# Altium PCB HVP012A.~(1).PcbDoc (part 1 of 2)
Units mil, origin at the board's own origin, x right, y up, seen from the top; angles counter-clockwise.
Board outline 2249 x 2178 mil, 4 copper layers (Top Layer, MidLayer1, MidLayer2, Bottom Layer), stack 61.2 mil thick; 92 components, 29 nets, 189 pads, 191 vias.
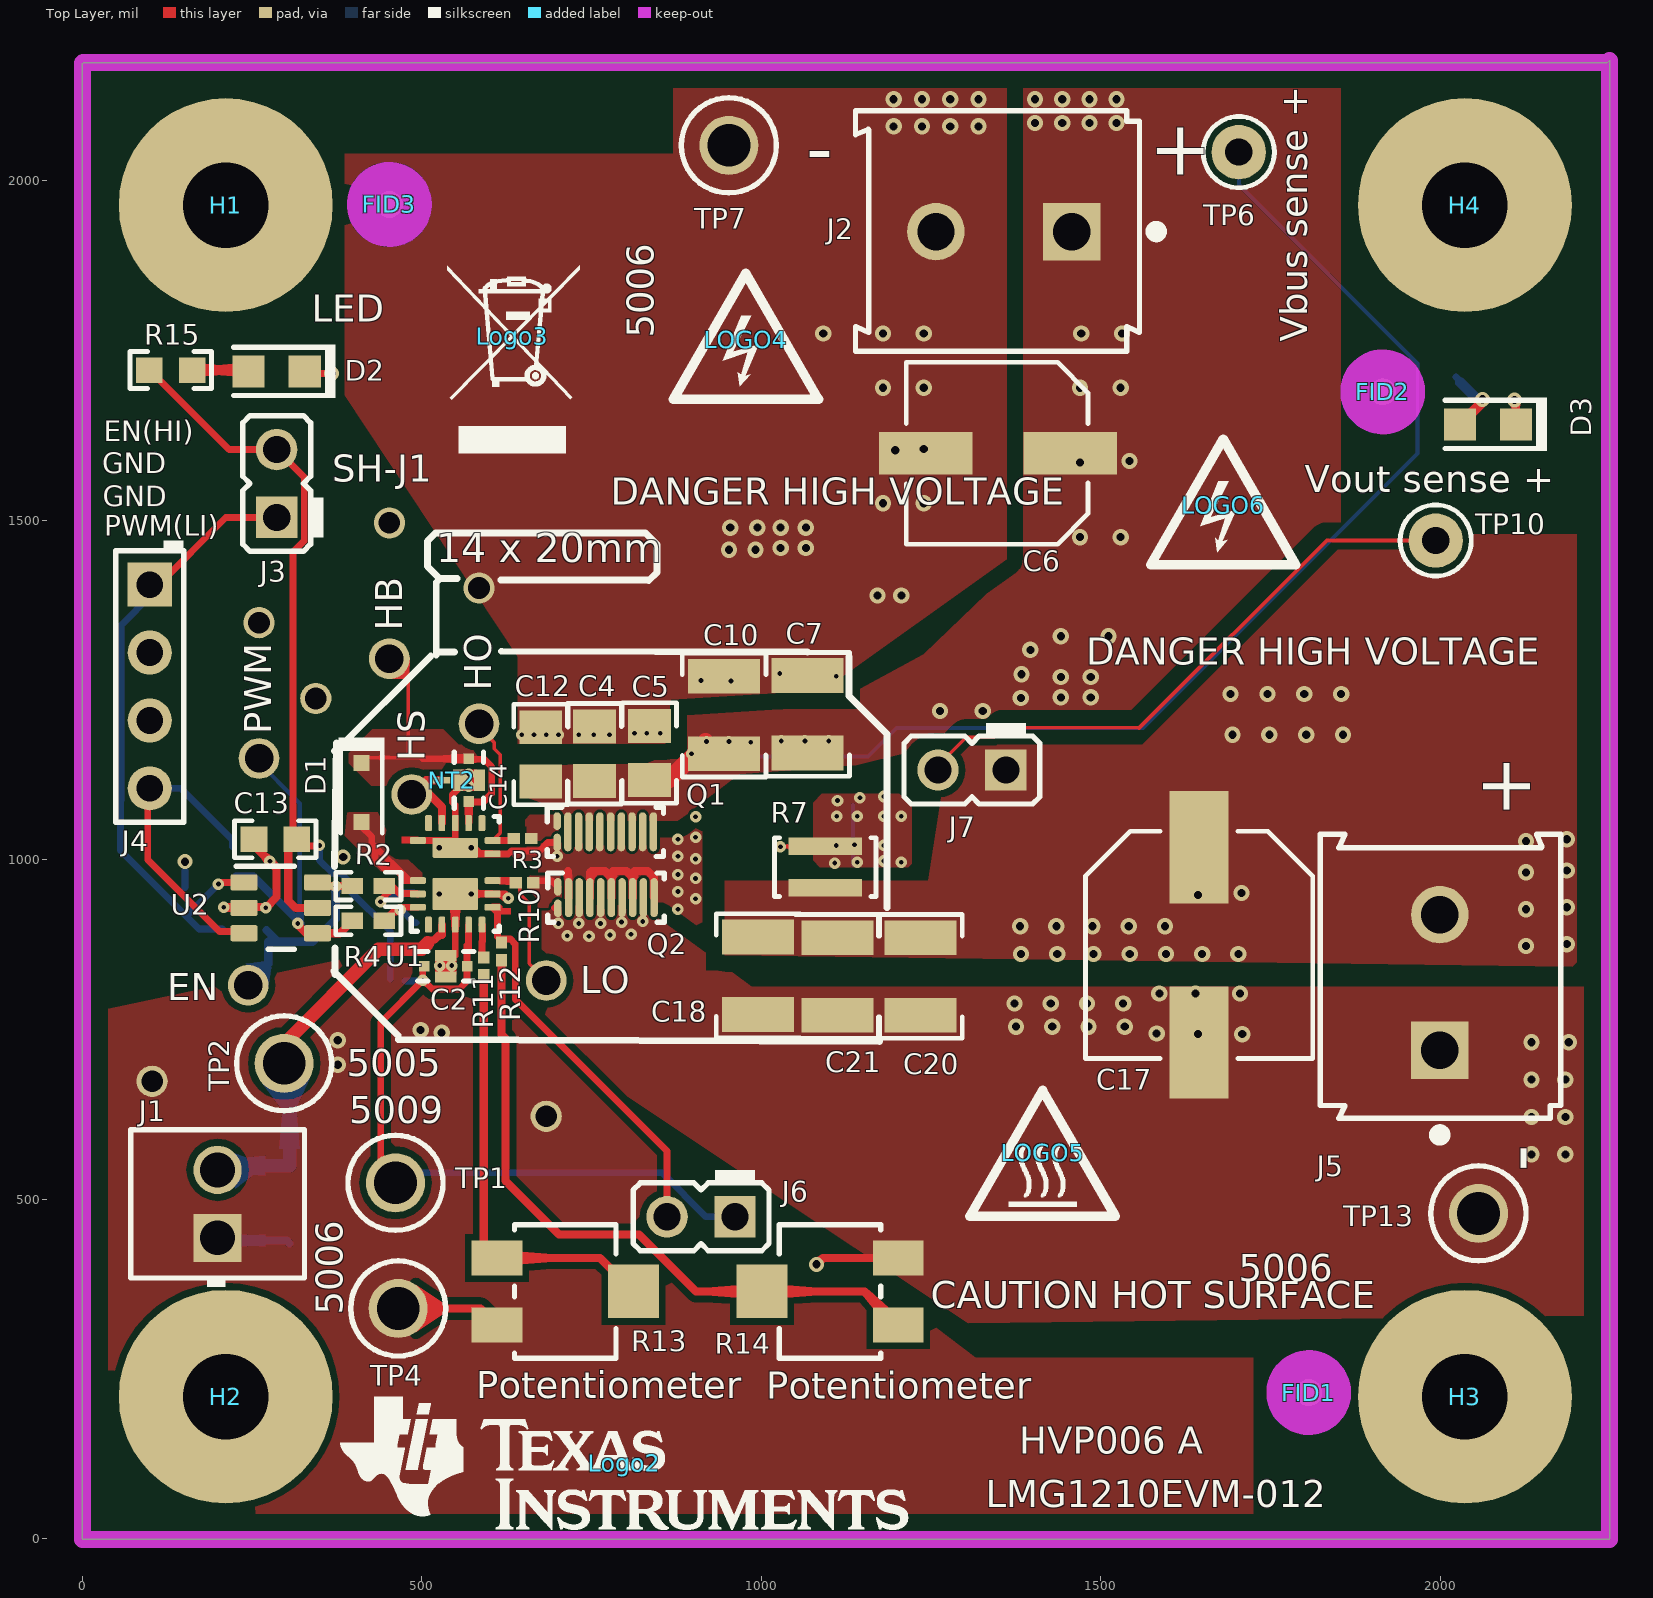
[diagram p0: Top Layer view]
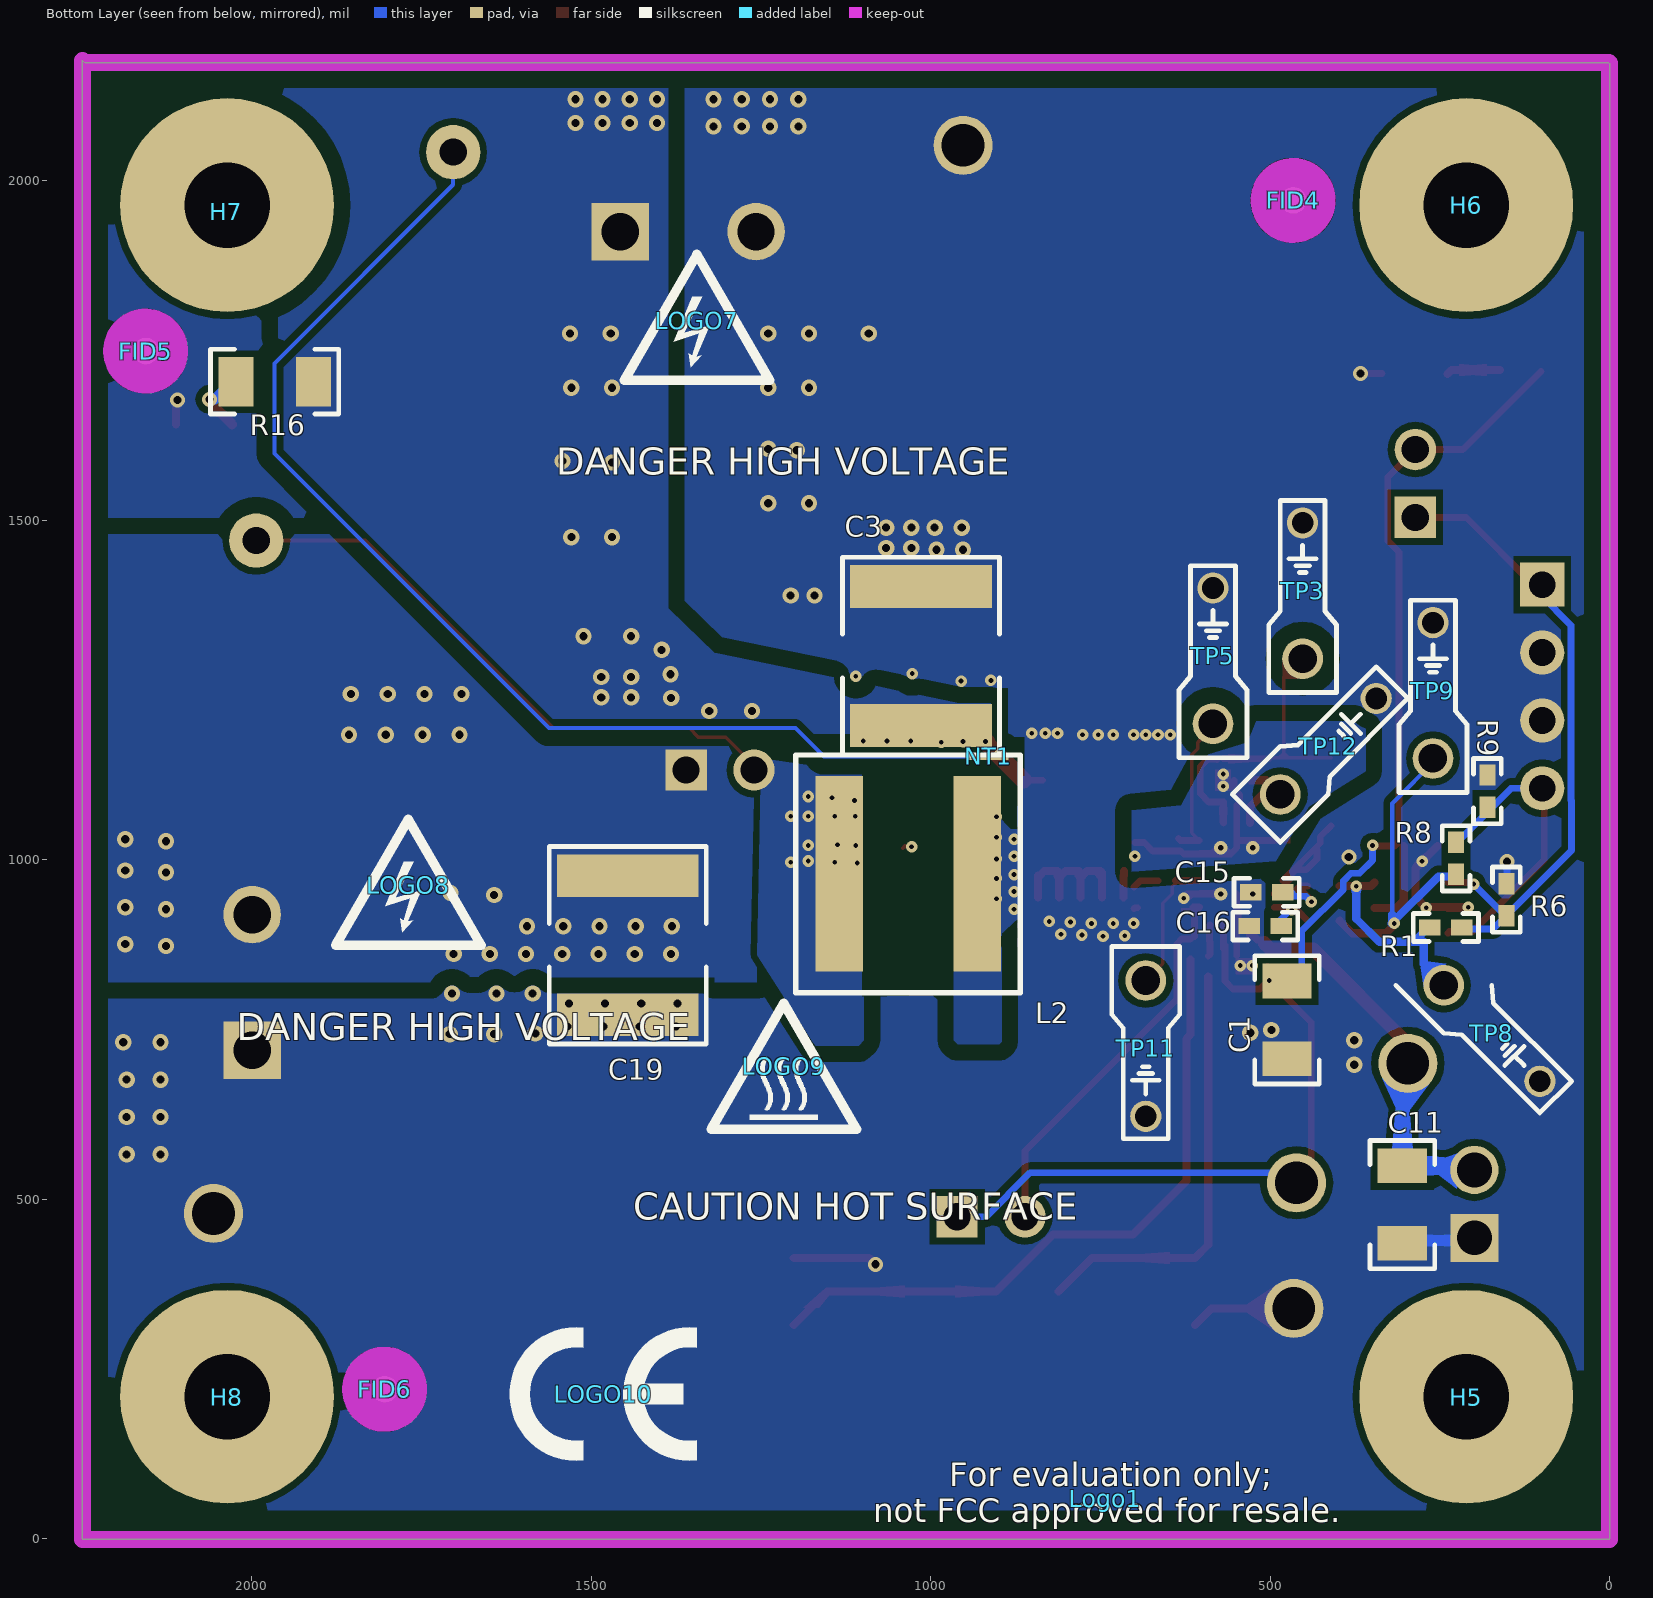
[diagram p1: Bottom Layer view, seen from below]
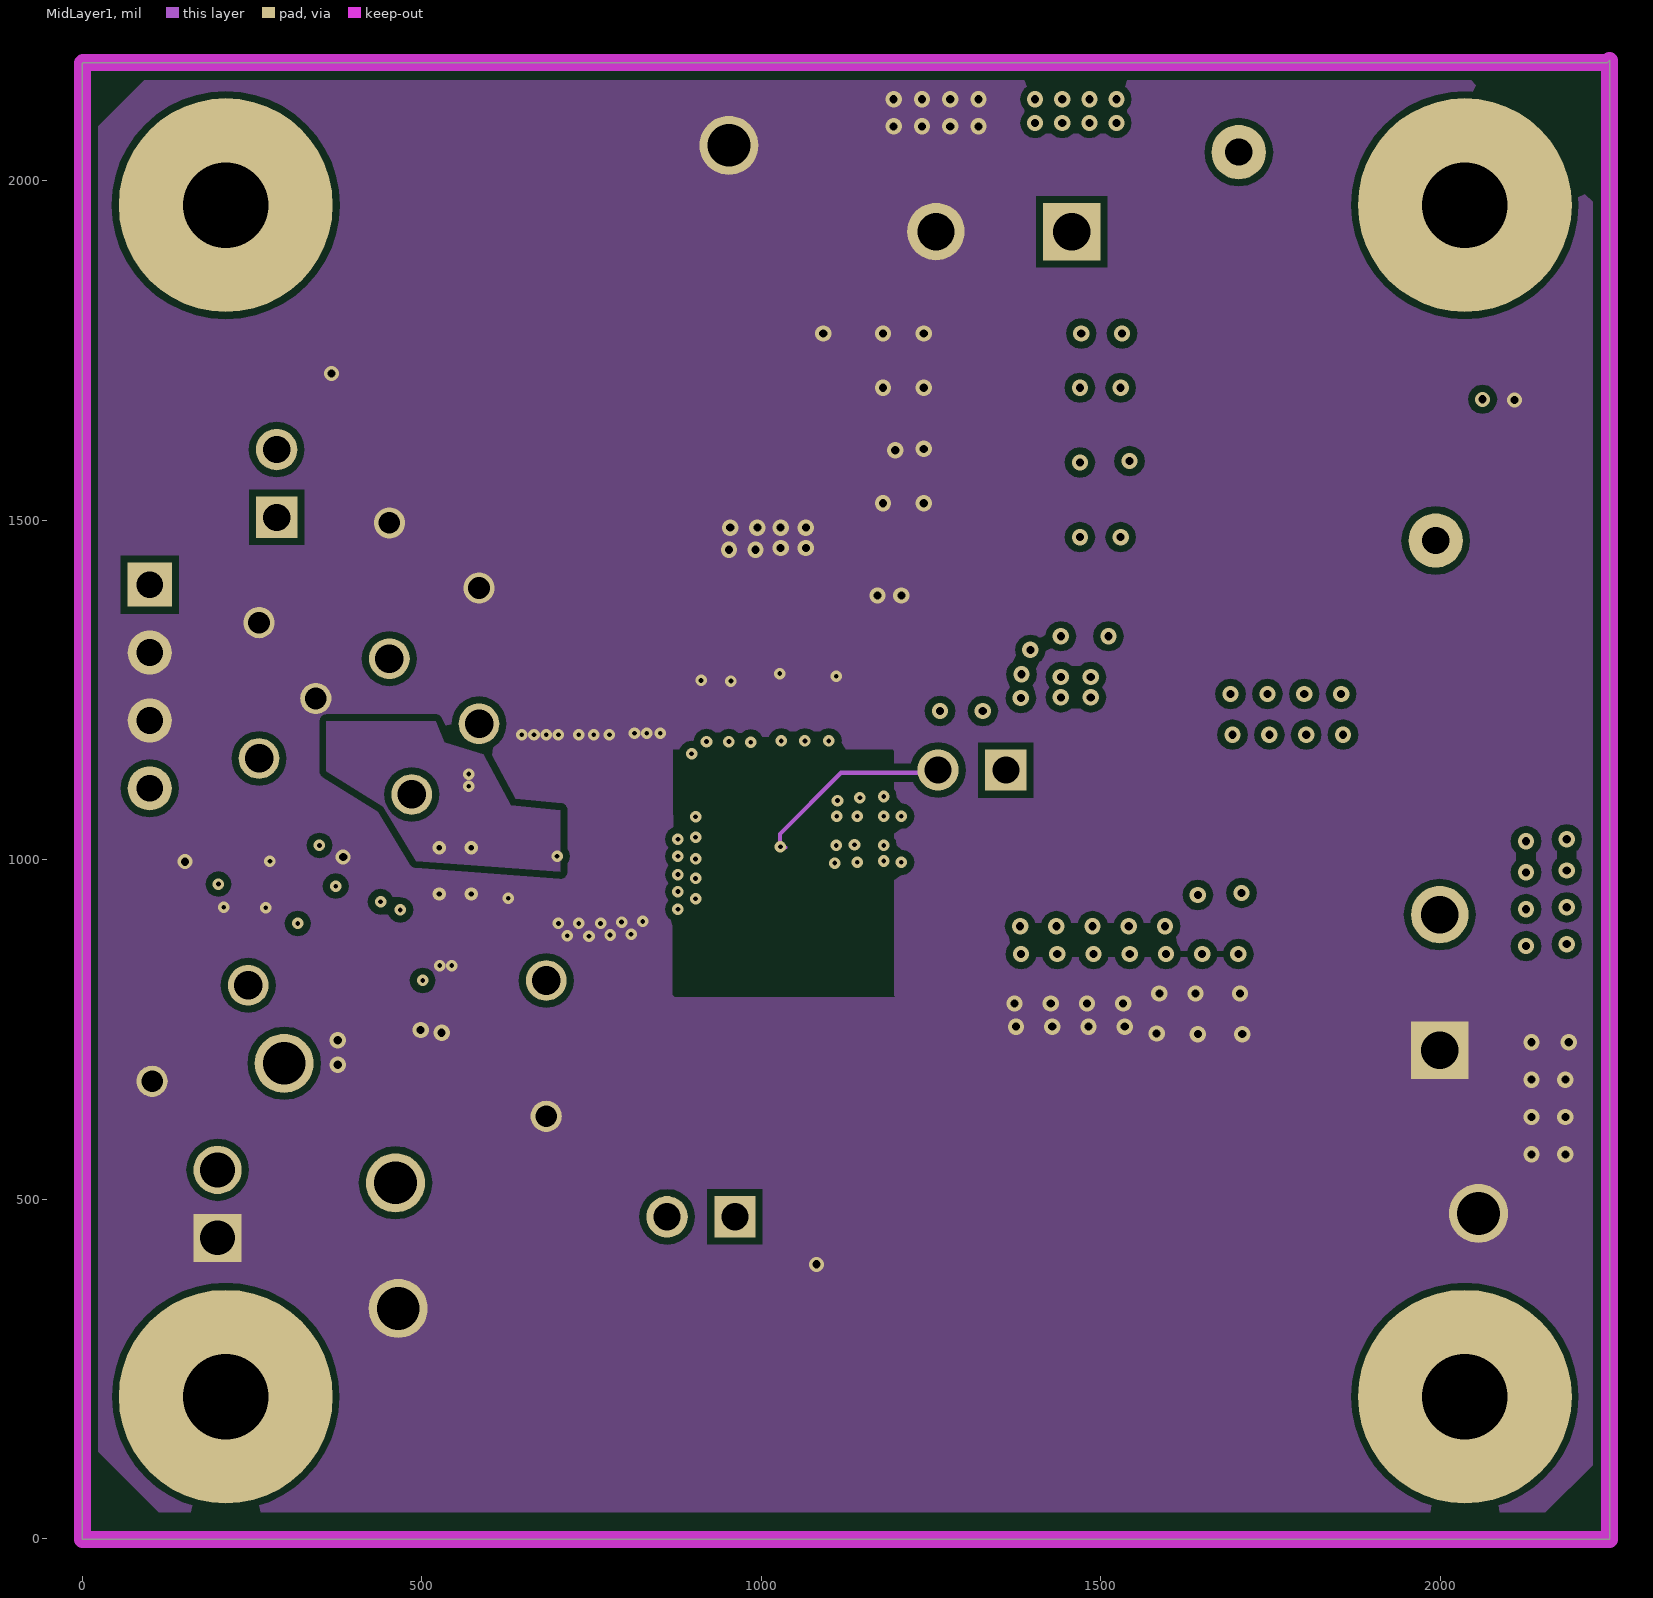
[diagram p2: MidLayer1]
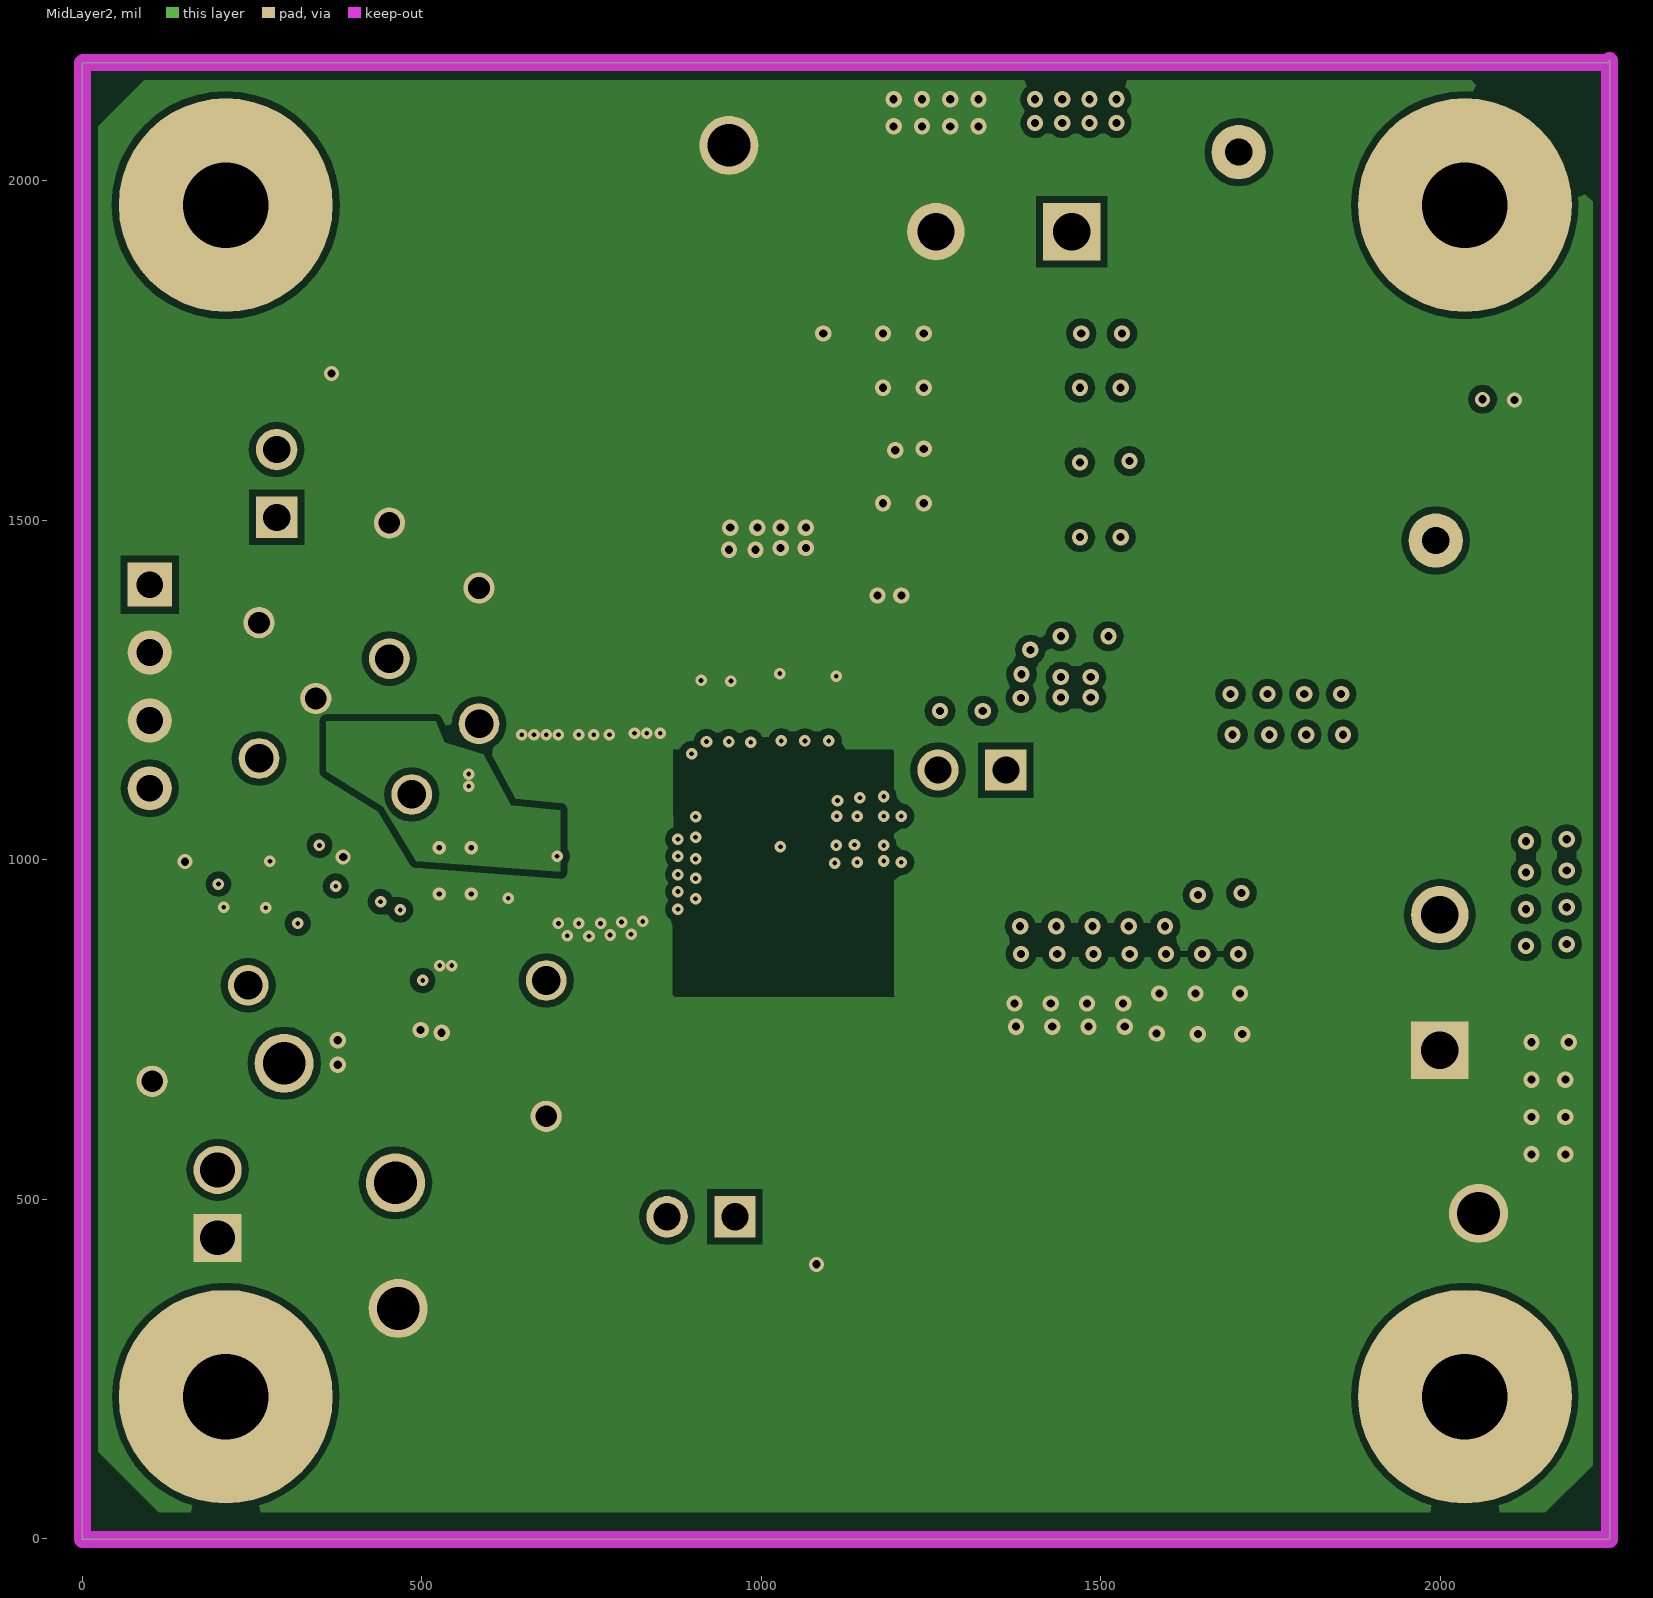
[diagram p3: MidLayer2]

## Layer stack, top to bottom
Top Solder: solder mask 0.4, Solder Resist, Dk 3.5
Top Layer: signal copper 2.8
Dielectric1: core 5, FR-4, Dk 4.2
MidLayer1: signal copper 2.8
Dielectric2: core 40, FR-4, Dk 4.2
MidLayer2: signal copper 2.8
Dielectric 3: prepreg 5, Dk 4.2
Bottom Layer: signal copper 2.8
Bottom Solder: solder mask 0.4, Solder Resist, Dk 3.5

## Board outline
0,-1 0,2173 1,2174 2246,2174 2249,2177 2249,-1

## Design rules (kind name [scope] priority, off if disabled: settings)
AcuteAngle [All] p1: minimum=3.20000000000000E+0001 checktracksonly=FALSE
AssemblyTestPointUsage [All] p1: valid=2
Clearance Fiducials [HasFootprint('Fiducial10-30')] p1: gap=0 ignorepadtopadclearanceinfootprint=FALSE
Clearance "inner layer clearance" [OnLayer('MidLayer1')or OnLayer('MidLayer2')] p2: gap=10 ignorepadtopadclearanceinfootprint=FALSE except(0: Arc-Hole Track-Hole SMDPad-Hole THPad-Hole Via-Hole Fill-Hole Poly-Hole Region-Hole Text-Hole)
Clearance Clearance_BoardEdge_Poly [OnCopper and InPoly vs IsKeepOut] p3: gap=25 ignorepadtopadclearanceinfootprint=FALSE except(0: Arc-Hole Track-Hole SMDPad-Hole THPad-Hole Via-Hole Fill-Hole Poly-Hole Region-Hole Text-Hole)
Clearance Clearance_BoardEdge [OnCopper and Not InComponentClass('Logo') and not InComponentClass('FiducialMark') and not InRegion(1000,500,4000,800) and Not OnLayer('Keepout') vs OnLayer('Keepout')] p4: gap=60 ignorepadtopadclearanceinfootprint=FALSE except(0: Arc-Hole Track-Hole SMDPad-Hole THPad-Hole Via-Hole Fill-Hole Poly-Hole Region-Hole Text-Hole)
Clearance Clearance_BoardEdge_MountingHoles [OnCopper and InComponentClass('Mounting Holes') vs IsKeepOut] p5: gap=40 ignorepadtopadclearanceinfootprint=FALSE except(0: Arc-Hole Track-Hole SMDPad-Hole THPad-Hole Via-Hole Fill-Hole Poly-Hole Region-Hole Text-Hole)
Clearance "FET pads clearance" [All vs WithinRoom('FETs')] p6: gap=4 ignorepadtopadclearanceinfootprint=FALSE except(0: Arc-Hole Track-Hole SMDPad-Hole THPad-Hole Via-Hole Fill-Hole Poly-Hole Region-Hole Text-Hole)
Clearance SW [InNetClass('SW') vs not InNetClass('SW')] p7: gap=24 ignorepadtopadclearanceinfootprint=FALSE except(0: Arc-Hole Track-Hole SMDPad-Hole THPad-Hole Via-Hole Fill-Hole Poly-Hole Region-Hole Text-Hole)
Clearance HV [InNetClass('HV') vs not InNetClass('HV')] p8: gap=24 ignorepadtopadclearanceinfootprint=FALSE except(0: Arc-Hole Track-Hole SMDPad-Hole THPad-Hole Via-Hole Fill-Hole Poly-Hole Region-Hole Text-Hole)
Clearance HV2 [InNetClass('HV2') vs not InNetClass('HV2')] p9: gap=24 ignorepadtopadclearanceinfootprint=FALSE except(0: Arc-Hole Track-Hole SMDPad-Hole THPad-Hole Via-Hole Fill-Hole Poly-Hole Region-Hole Text-Hole)
Clearance Clearance_Poly [InPolygon] p10: gap=10 ignorepadtopadclearanceinfootprint=FALSE except(0: Arc-Hole Track-Hole SMDPad-Hole THPad-Hole Via-Hole Fill-Hole Poly-Hole Region-Hole Text-Hole)
Clearance Clearance_1 [All] p11: gap=5 ignorepadtopadclearanceinfootprint=FALSE except(0: Arc-Hole Track-Hole SMDPad-Hole THPad-Hole Via-Hole Fill-Hole Poly-Hole Region-Hole Text-Hole)
ComponentClearance [InComponent('SH-J1')] p1: gap=0 collisioncheckmode=3 verticalgap=0 showdistances=FALSE
ComponentClearance "Schematic ComponentClearance1" [InComponent('NT1')] p2: gap=0 collisioncheckmode=3 verticalgap=0 showdistances=FALSE
ComponentClearance "Schematic ComponentClearance2" [InComponent('NT2')] p3: gap=0 collisioncheckmode=3 verticalgap=0 showdistances=FALSE
ComponentClearance ComponentClearance_ScrewToNut [(HasFootprint('NY PMS 440 0025 PH')) vs (HasFootprint('Keystone_1902C'))] p4: gap=0 collisioncheckmode=3 verticalgap=0 showdistances=FALSE
ComponentClearance ComponentClearance_testpoint [(HasFootprint('TESTPOINT_PIGTAIL'))] p5: gap=0 collisioncheckmode=3 verticalgap=0 showdistances=FALSE
ComponentClearance not_comp_1 [WithinRoom('not_comp')] p6: gap=0 collisioncheckmode=3 verticalgap=0 showdistances=FALSE
ComponentClearance ComponentClearance_1 [All] p7: gap=10 collisioncheckmode=3 verticalgap=10 showdistances=FALSE
ComponentClearance ComponentClearance_Shunt [InComponentClass('Header') vs InComponentClass('Shunt')] p8: gap=0 collisioncheckmode=3 verticalgap=0 showdistances=FALSE
ComponentClearance ComponentClearance_Logo [InComponentClass('Logo')] p9: gap=50 collisioncheckmode=3 verticalgap=10 showdistances=FALSE
ComponentClearance ComponentClearance_MountingHoles [InComponentClass('Mounting Holes')] p10: gap=0 collisioncheckmode=3 verticalgap=100000 showdistances=FALSE
ComponentClearance ComponentClearance_SmallPassives [HasFootprint('0201*') or HasFootprint('0402*') or HasFootprint('0508') or HasFootprint('0603*') or HasFootprint('0612') or HasFootprint('0805*') or HasFootprint('0815*') or HasFootprint('0830*') or HasFootprint('1206*') or HasFootprint('1210*') or HasFootprint('1808*') or HasFootprint('1812*') or HasFootprint('1825*') or HasFootprint('2010*') or HasFootprint('2220*') or HasFootprint('2225*') or HasFootprint('2512*') or HasFootprint('2728*') or HasFootprint('3518*') vs HasFootprint('0201*') or HasFootprint('0402*') or HasFootprint('0508') or HasFootprint('0603*') or HasFootprint('0612') or HasFootprint('0805*') or HasFootprint('0815*') or HasFootprint('0830*') or HasFootprint('1206*') or HasFootprint('1210*') or HasFootprint('1808*') or HasFootprint('1812*') or HasFootprint('1825*') or HasFootprint('2010*') or HasFootprint('2220*') or HasFootprint('2225*') or HasFootprint('2512*') or HasFootprint('2728*') or HasFootprint('3518*')] p11: gap=5 collisioncheckmode=3 verticalgap=10 showdistances=FALSE
ComponentClearance ComponentClearance_THtoSMT [IsThruComponent vs IsSMTComponent] p12: gap=40 collisioncheckmode=3 verticalgap=30 showdistances=FALSE
ComponentClearance ComponentClearance_THtoTH [IsThruComponent vs IsThruComponent] p13: gap=118.11 collisioncheckmode=3 verticalgap=30 showdistances=FALSE
DiffPairsRouting [All] p1: maxlimit=100 minlimit=10 mostfreqgap=10 toplayer_minwidth=15 toplayer_maxwidth=15 toplayer_prefwidth=15 midlayer1_minwidth=15 midlayer1_maxwidth=15 midlayer1_prefwidth=15 midlayer2_minwidth=15 midlayer2_maxwidth=15 midlayer2_prefwidth=15 bottomlayer_minwidth=15 bottomlayer_maxwidth=15 bottomlayer_prefwidth=15 maxuncoupledlength=1000
FabricationTestPointUsage TestPointUsage [All] p1: valid=2 allowmultiple=FALSE
FabricationTestpoint Testpoint [All] p1: side=3 testpointundercomponent=TRUE minsize=40 maxsize=100 preferedsize=60 minholesize=0 maxholesize=40 preferedholesize=32 testpointgrid=1 allowsidetop=TRUE allowsidebottom=TRUE usegrid=TRUE gridtolerance=0.01
FanoutControl Fanout_LCC [IsLCC] p1: bgadir=Out bgaviamode=Centered fanoutstyle=Auto fanoutdirection=Alternating viagrid=1 // Fanout_LCC (Default Rule)
FanoutControl Fanout_BGA [IsBGA] p2: bgadir=Out bgaviamode=Centered fanoutstyle=Auto fanoutdirection=Alternating viagrid=1 // Fanout_BGA (Default Rule)
FanoutControl Fanout_Default [All] p4: bgadir=Out bgaviamode=Centered fanoutstyle=Auto fanoutdirection=Alternating viagrid=1 // Fanout_Default (Default Rule)
FanoutControl Fanout_Small [(CompPinCount < 5)] p5: bgadir=Out bgaviamode=Centered fanoutstyle=Auto fanoutdirection=OutThenIn viagrid=1 // Fanout_Small (Default Rule)
HoleSize [All] p1: absolutevalues=TRUE maxlimit=251 minlimit=7 maxpercent=80.000 minpercent=20.000
HoleToHoleClearance [All] p1: gap=6 allowstackedmicrovias=TRUE
MinimumAnnularRing MinimumAnnularRing_ThermalPadVias [IsVia and InAnyComponent] p1: minimumring=5
MinimumAnnularRing [All] p2: minimumring=5
MinimumSolderMaskSliver MinimumSolderMaskSliver_Logo [InComponentClass('Logo') vs InComponentClass('Logo')] p1: minsoldermaskwidth=0.7
MinimumSolderMaskSliver [All] p2: minsoldermaskwidth=1
PlaneConnect [All] p1: planeconnectstyle=Direct reliefexpansion=10 reliefentries=4 reliefconductorwidth=10 reliefairgap=10
PolygonConnect [All] p1: connectstyle=Direct reliefconductorwidth=10 reliefentries=4 polygonreliefangle="90 Angle" airgapwidth=10
RoomDefinition FETs [InComponent('No Component')] p1: confinementstyle=ConfineIn formatcopy=TRUE lockcomponents=FALSE outline 636,1077 646,1077 646,873 921,873 921,1076
RoutingVias ThermalPadVias [IsVia and InAnyComponent] p1: holewidth=7.87 width=19.68 viastyle="Through Hole" minholewidth=7 minwidth=19.68 maxholewidth=12.99 maxwidth=23.62
RoutingVias [All] p2: holewidth=16 width=18 viastyle="Through Hole" minholewidth=6.99 minwidth=13 maxholewidth=40 maxwidth=65
SMDToCorner [All] p1: distance=30000
SilkToSilkClearance [All] p1: silktosilkclearance=2
SilkToSolderMaskClearance SilkscreenOverComponentPads [IsPad] p1: minsilkscreentomaskgap=2 clearancetoexposedcopper=TRUE
SolderMaskExpansion [All] p1: expansion=1.97
Width [All] p1: maxlimit=200 minlimit=3 preferedwidth=6 checkconnectedcopper=TRUE
15 further rules are at their usual default settings.

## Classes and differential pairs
net class HV: K_VIN VIN
net class SW: 11 15 HB2 HGATE HO HS2 NetNT2_1
net class HV2: NetJ7_2 VOUT

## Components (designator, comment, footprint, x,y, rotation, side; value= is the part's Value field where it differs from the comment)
C1 "Capacitor" 1206 475,764 r270 bottom value=10uF
C2 "Capacitor_Balanced" YFF18PW 535,843 r0 top value=0.47uF
C3 "Capacitor" 2220_200 1014,1300 r90 bottom value=1uF
C4 "Capacitor" 0805_HV 754,1156 r90 top value=0.022uF
C5 "Capacitor" 0805_HV 835,1157 r90 top value=0.022uF
C6 "Cap_Polarized" CAPSMT_62_F60 1349,1599 r180 top value=22uF
C7 "Capacitor" 1210_220 1068,1214 r90 top value=0.22uF
C10 "Capacitor" 1210_220 945,1213 r90 top value=0.22uF
C11 "Capacitor" 1206 305,492 r90 bottom value=10uF
C12 "Capacitor" 0805_HV 675,1155 r90 top value=0.022uF
C13 "Capacitor" 0603 284,1030 r180 top value=0.1uF
C14 "Capacitor_Balanced" YFF18PW 569,1117 r90 top value=0.47uF
C15 "Capacitor" 0402 505,952 r180 bottom value=10pF
C16 "Capacitor" 0402 507,902 r0 bottom value=10pF
C17 "Cap_Polarized" CAPSMT_62_H70 1644,875 r270 top value=47uF
C18 "Capacitor" 1210_220 995,829 r270 top value=0.22uF
C19 "Capacitor" 2220_200 1446,874 r270 bottom value=1uF
C20 "Capacitor" 1210_220 1234,828 r270 top value=0.22uF
C21 "Capacitor" 1210_220 1112,828 r270 top value=0.22uF
D1 "BAT46WJ,115" SOD-323F 411,1099 r270 top value=100V
D2 "LED" LTST-C170KGKT_Green 286,1719 r0 top value=Green
D3 "green" LTST-C170KGKT_Green 2070,1641 r0 top value=Green
FID1 "Fiducial" Fiducial10-30 1806,215 r0 top
FID2 "Fiducial" Fiducial10-30 1915,1689 r0 top
FID3 "Fiducial" Fiducial10-30 452,1965 r0 top
FID4 "Fiducial" Fiducial10-30 466,1971 r180 bottom
FID5 "Fiducial" Fiducial10-30 2156,1749 r180 bottom
FID6 "Fiducial" Fiducial10-30 1804,220 r180 bottom
H1 "NY PMS 440 0025 PH" "NY PMS 440 0025 PH" 211,1964 r0 top
H2 "NY PMS 440 0025 PH" "NY PMS 440 0025 PH" 211,209 r0 top
H3 "NY PMS 440 0025 PH" "NY PMS 440 0025 PH" 2036,209 r0 top
H4 "NY PMS 440 0025 PH" "NY PMS 440 0025 PH" 2036,1964 r0 top
H5 "Nut" Keystone_1902C 211.18,208.51 r180 bottom
H6 "Nut" Keystone_1902C 211.18,1963.51 r180 bottom
H7 "Nut" Keystone_1902C 2037.18,1954.51 r180 bottom
H8 "Nut" Keystone_1902C 2036.18,208.51 r180 bottom
J1 "Receptacle_2x1" On-Shore_OSTVN02A150 199,493 r90 top
J2 "Receptacle_2x1" TEC_282841-2 1357,1925 r180 top
J3 "Header_2x1" Sullins_Gxx02SAAN 286,1554 r90 top
J4 "Header_4x1" TE_5-146278-4 99,1255 r270 top
J5 "Receptacle_2x1" TEC_282841-2 1999,819 r90 top
J6 "Header_2x1" Sullins_Gxx02SAAN 911,474 r180 top
J7 "Header_2x1" Sullins_Gxx02SAAN 1310,1132 r180 top
L2 "Inductor_Iron" XAL8080 1033,979 r0 bottom value=4.7uH
Logo1 "FCC disclaimer" FCC_disclaimer_stacked 742.47,58.47 r180 bottom
Logo2 "Texas Instruments" TI_Stacked_Overlay_Small 798,111 r0 top
Logo3 "WEEE logo" WEEE_Minimum 633,1771 r0 top
LOGO4 "DANGER HIGH VOLTAGE" IEC_HighVoltage_Small 977,1766 r0 top
LOGO5 "CAUTION HOT SURFACE" IEC_HotSurface_Small 1414,568 r0 top
LOGO6 "DANGER HIGH VOLTAGE" IEC_HighVoltage_Small 1680,1522 r0 top
LOGO7 "DANGER HIGH VOLTAGE" IEC_HighVoltage_Small 1344,1794 r180 bottom
LOGO8 "DANGER HIGH VOLTAGE" IEC_HighVoltage_Small 1769,962 r180 bottom
LOGO9 "CAUTION HOT SURFACE" IEC_HotSurface_Small 1216,696 r180 bottom
LOGO10 "CE Mark" CE_Mark_5mm 1482,213 r180 bottom
NT1 "Net-Tie" Net-Tie_10milWide_30milLong 915,1152 r0 bottom net-tie
NT2 "Net-Tie" Net-Tie_10milWide_30milLong 544,1117 r0 top net-tie
Q1 "EPC2001C" EPC2001 770,1041 r0 top value=100V
Q2 "EPC2001C" EPC2001 771,944 r0 top value=100V
R1 "Resistor" 0402 241,900 r0 bottom value=0
R2 "Resistor" 0402 421,961 r0 top value=0
R3 "Resistor" 0201 648,1031 r0 top value=0
R4 "Resistor" 0402 421,910 r0 top value=0
R6 "Resistor" 0402 152,941 r270 bottom value=20.0k
R7 "PRL1632-R005-F-T1" 0612 1094,989 r270 top value=0.005
R8 "Resistor" 0402 226,1002 r270 bottom value=0
R9 "Resistor" 0402 180,1101 r270 bottom value=20.0k
R10 "Resistor" 0201 651,966 r0 top value=0
R11 "Resistor" 0201 591,843 r90 top value=20.0k
R12 "Resistor" 0201 617,865 r90 top value=20.0k
R13 "Potentiometer" TRIM_3224X 711,364 r0 top value=1M
R14 "Potentiometer" TRIM_3224X 1101,364 r180 top value=1M
R15 "Resistor" 0603 130,1721 r0 top value=1.0k
R16 "Resistor" 1206 1966,1704 r0 bottom value=100k
SH-J1 "SNT-100-BK-G" SNT-100-BK-G 287,1546 r90 top value=1x2
TP1 "5009" Keystone5009 461,524 r0 top
TP2 "5005" Keystone5005 297,700 r0 top
TP3 "HB" TESTPOINT_PIGTAIL 452,1296 r0 bottom
TP4 "5006" Keystone5006 465,339 r0 top
TP5 "HO" TESTPOINT_PIGTAIL 584,1200 r0 bottom
TP6 "Vbus sense +" Keystone5000 1703,2042 r0 top
TP7 "5006" Keystone5006 952,2052 r90 top
TP8 "EN" TESTPOINT_PIGTAIL 244,815 r135 bottom
TP9 "PWM" TESTPOINT_PIGTAIL 260,1149 r0 bottom
TP10 "Vout sense +" Keystone5000 1993,1470 r0 top
TP11 "LO" TESTPOINT_PIGTAIL 683,822 r180 bottom
TP12 "HS" TESTPOINT_PIGTAIL 485,1096 r45 bottom
TP13 "5006" Keystone5006 2056,479 r90 top
U1 "LMG1210" RVR0019A 549,979 r90 top
U2 "SN74LVC2G17DBVR" DBV0006A_N 292,929 r0 top
ZZ2 "These assemblies are ESD sensitive, ESD precautions shall be observed." AssemblyNote -714,3598.11 r0 top
ZZ3 "These assemblies must be clean and free from flux and all contaminants. Use of no clean flux is not acceptable." AssemblyNote -714,3509.56 r0 top
ZZ4 "These assemblies must comply with workmanship standards IPC-A-610 Class 2, unless otherwise specified." AssemblyNote -714,3421 r0 top

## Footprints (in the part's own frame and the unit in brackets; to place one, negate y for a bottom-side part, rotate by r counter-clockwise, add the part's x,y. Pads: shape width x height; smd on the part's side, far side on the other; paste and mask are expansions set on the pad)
0201 [mm] "Data from Kemet datasheet CC101_COM dated 7/28/11"
  rect 0.46x0.42 smd mask+0.048: 1(-0.33,0) 2(0.33,0)
  body extent -0.31,-0.16 0.31,0.16, height 0.26
0402 [mm] "0402 from SM-752 data"
  rect 0.8x0.6 smd: 1(-0.6,0) 2(0.6,0)
  silkscreen extent -1.22,-0.52 1.22,0.52, body extent -0.55,-0.3 0.55,0.3, height 0.6
0603 [mm] "0603 from SM-752 data"
  rect 1x0.95 smd: 1(-0.8,0) 2(0.8,0)
  silkscreen extent -1.52,-0.69 1.52,0.69, body extent -0.87,-0.47 0.87,0.47, height 1
0612 [mm] "Panasonic recommended land pattern, fb97d03ed01.pdf dated April 2008"
  rect 0.65x2.75 smd: 1(-0.775,0) 2(0.775,0)
  silkscreen extent -1.1,-1.9 1.1,1.9, body extent -0.9,-1.7 0.9,1.7, height 0.85
0805_HV [mil] "0805 with 30mil clearance between pads"
  rect 50x63 smd: 1(-40,0) 2(40,0)
  silkscreen extent -74,-40 74,40, body extent -43,-29 43,29, height 57
1206 [mm] "1206 from SM-752 data"
  rect 1.3x1.85 smd: 1(-1.45,0) 2(1.45,0)
  silkscreen extent -2.4,-1.21 2.4,1.21, body extent -1.7,-0.9 1.7,0.9, height 1.35
1210_220 [mm] "1210"
  rect 1.3x2.7 smd: 1(-1.45,0) 2(1.45,0)
  silkscreen extent -2.32,-1.57 2.32,1.57, body extent -1.7,-1.35 1.7,1.35, height 2.2
2220_200 [mm] "Chip Capacitor, Body 5.7x5.0mm, IPC Medium Density"
  rect 1.6x5.3 smd: 1(-2.6,0) 2(2.6,0)
  silkscreen extent -3.69,-2.94 3.69,2.94, body extent -2.95,-2.62 2.95,2.62, height 1.35
AssemblyNote [mil] "Assembly Note"
CAPSMT_62_F60 [mm] "6.3 x 5.7mm:  Chemi-Con F60"
  rect 3.5x1.6 smd: 1(-2.688,0.012) 2(2.712,0.012)
  silkscreen extent -3.35,-3.39 3.45,3.41, body extent -3.39,-3.39 3.45,3.41, height 6
CAPSMT_62_H70 [mm] "8 x 6.7mm:  Chemi-Con H70"
  rect 4.2x2.2 smd: 1(-3.638,0.012) 2(3.662,0.012)
  silkscreen extent -4.24,-4.24 4.26,4.26, body extent -4.24,-4.24 4.26,4.26, height 7
CE_Mark_5mm [mil] "Minimum text height for CE Mark"
  silkscreen extent -138,-98 138,98
DBV0006A_N [mm] "SOT23, 6-Leads, Body 2.9x1.6mm, Pitch 0.95mm, Lead Span 2.8mm, IPC Medium Density"
  rrect17% 1x0.6 smd: 1(-1.375,0.95) 2(-1.375,0) 3(-1.375,-0.95) 4(1.375,-0.95) 5(1.375,0) 6(1.375,0.95)
  silkscreen extent -1.68,-1.55 0.5,1.55, body extent -1.42,-1.46 1.42,1.46, height 1.12
EPC2001 [mm] "SMD, 11-Leads, Body 4.105x1.632mm, Pitch 0.4mm"
  oval 0.28x0.66 smd paste-0.05 mask-0.05: 1(-1.8,0.401) 2(-1.8,-0.401)
  oval 0.28x1.462 smd paste-0.05 mask-0.05: 3(-1.4,0) 4(-1,0) 5(-0.6,0) 6(-0.2,0) 7(0.2,0) 8(0.6,0) 9(1,0) 10(1.4,0) 11(1.8,0)
  silkscreen extent -2.18,-0.92 2.17,0.92, body extent -2.07,-0.83 2.07,0.83, height 0.82
FCC_disclaimer_stacked [mil]
Fiducial10-30 [mm]
  round 1 smd mask+1: 1(0,0)
  Top Layer keep-out circle w1.678: c0,0 r0.75
IEC_HighVoltage_Small [mil]
  silkscreen extent -107,-88 107,97
IEC_HotSurface_Small [mil]
  silkscreen extent -107,-93 107,92
Keystone5000 [mil] "For Keystone 500x miniature loop terminals"
  round 80 hole 40: 1(0,0)
  silkscreen extent -52,-52 52,52, body extent -49,-49 49,49, height 182
Keystone5005 [mil] "Keystone Compact loops"
  round 87 hole 63: 1(0,0)
  silkscreen extent -70,-70 70,70, body extent -63,-63 62,63, height 225
Keystone5006 [mil] "Keystone Compact loops"
  round 87 hole 63: 1(0,0)
  silkscreen extent -70,-70 70,70, body extent -63,-63 62,63, height 225
Keystone5009 [mil] "Keystone Compact loops"
  round 87 hole 63: 1(0,0)
  silkscreen extent -70,-70 70,70, body extent -63,-63 62,63, height 225
Keystone_1902C [mil] "Hex Standoff, 4-40 threaded, nylon"
  round 1 on Mech4: 0(0,0)
  body extent -145,-126 146,126, height 501
LTST-C170KGKT_Green [mm] "LITE-ON"
  rect 1.2x1.2 smd: 1(-1.05,0) 2(1.05,0)
  silkscreen extent -1.6,-1 2.2,1, body extent -1.05,-0.67 1.05,0.67, height 1.1
Net-Tie_10milWide_30milLong [mil] "10mil net tie, no solder mask opening, no solder paste"
  rect 30x10 smd paste-5 mask-5: 1(-15,0) 2(15,0)
"NY PMS 440 0025 PH" [mm] "4-40 nylon screw and mounting hole"
  round 8 hole 3.2: 1(0,0)
  body extent -3.3,-3.3 3.3,3.3, height 2.69
On-Shore_OSTVN02A150 [mm] "Terminal Block, 2.54mm, 2-pole, Brass, TH"
  rect 1.8x1.8 hole 1.3: 1(-1.27,0)
  round 1.8 hole 1.3: 2(1.27,0)
  silkscreen extent -3.1,-3.25 2.77,3.25, body extent -2.77,-3.25 2.77,3.25, height 8.51
RVR0019A [mm] "QFN, 19-Leads, Body 3x4mm, Pitch 0.5mm"
  rrect40% 0.6x0.25 smd: 1(-1.9,1) 2(-1.9,0.5) 3(-1.9,0) 4(-1.9,-0.5) 5(-1.9,-1) 11(1.9,-1) 12(1.9,-0.5) 13(1.9,0) 14(1.9,0.5) 15(1.9,1)
  rrect40% 0.25x0.6 smd: 6(-1.25,-1.4) 7(-0.75,-1.4) 8(-0.25,-1.4) 9(0.75,-1.4) 10(1.25,-1.4) 16(1.25,1.4) 17(-0.25,1.4) 18(-0.75,1.4) 19(-1.25,1.4)
  rrect13% 1.13x0.75 on Top Paste: 20(-0.75,-0.475) 20(-0.75,0.475)
  rrect8% 1.2x1.7 smd paste-1.7: 20(-0.75,0)
  rrect13% 0.71x0.75 on Top Paste: 21(0.975,-0.475) 21(0.975,0.475)
  rrect13% 0.75x1.7 smd paste-1.7: 21(0.975,0)
  silkscreen extent -2.15,-1.65 2.15,1.65, body extent -2,-1.5 2,1.5, height 0.8
SNT-100-BK-G [mil] "Samtec STEP model"
  round 1 on Mech3: 0(0,0)
  body extent -100,-50 100,50, height 344
SOD-323F [mm] "NXP recommended land pattern"
  rect 0.6x0.6 smd paste-0.05: 1(-1.1,0) 2(1.1,0)
  silkscreen extent -2.06,-0.86 1.53,0.86, body extent -1.35,-0.67 1.35,0.68, height 0.79
Sullins_Gxx02SAAN [mm] "Header, 2.54 mm, 2x1, TH"
  rect 1.55x1.55 hole 1.016: 1(-1.27,0)
  round 1.55 hole 1.016: 2(1.27,0)
  silkscreen extent -2.54,-1.75 2.54,1.27, body extent -2.54,-1.27 2.54,1.27, height 8.38
TE_5-146278-4 [mm] "TE CONNECTIVITY"
  rect 1.65x1.65 hole 1: 1(-3.81,0)
  round 1.65 hole 1: 2(-1.27,0) 3(1.27,0) 4(3.81,0)
  silkscreen extent -5.46,-1.27 5.08,1.27, body extent -4.95,-1.17 4.95,1.17, height 8.13
TEC_282841-2 [mm] "TE Connectivity"
  rect 2.15x2.15 hole 1.4: 1(-2.54,0)
  round 2.15 hole 1.4: 2(2.54,0)
  silkscreen extent -5.9,-4.52 5.55,4.47, body extent -5.08,-4.52 5.58,4.48, height 15.2
TESTPOINT_PIGTAIL [mil] "Pigtail"
  round 60 hole 42: 1(0,0)
  round 46 hole 32: 2(0,-200)
  silkscreen extent -50,-233 50,50
TI_Stacked_Overlay_Small [mil]
  silkscreen extent -418,-98 418,98
TRIM_3224X [mm] "Bourns"
  rect 1.9x1.3 smd: 1(-2.55,1.25) 3(-2.55,-1.25)
  rect 1.9x2 smd: 2(2.55,0)
  silkscreen extent -1.9,-2.5 1.9,2.5, body extent -1.8,-2.4 1.8,2.4, height 5.31
WEEE_Minimum [mil] "WEEElie bin"
  silkscreen extent -95,-172 99,104
XAL8080 [mm] "Coilcraft"
  rect 1.78x7.31 smd: 1(-2.58,0) 2(2.58,0)
  silkscreen extent -4.2,-4.45 4.2,4.45, body extent -4.15,-4.4 4.15,4.4, height 8
YFF18PW [mm] "TDK"
  rect 0.4x0.4 smd: 1(-0.8,0) 2(0.8,0)
  rect 0.8x0.4 smd: 3(0,-0.4) 3(0,0.4)
  Top Layer region: -0.4,-0.3 0.4,-0.3 0.4,0.3 -0.4,0.3
  silkscreen extent -1.05,-0.55 1.05,0.55, body extent -0.85,-0.45 0.85,0.45, height 0.7

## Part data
C1 C11: library part CMP-0008574-2, "CAP, CERM, 10 uF, 25 V, +/- 10%, X7R, 1206", Cap_Case=1206, Manufacturer="Wurth Elektronik", PartNumber=885012208069, Supplier Part Number 1=732-7574-1-ND, TempCo=X7R, Tolerance_%=10%, Value1=Unknown, Value2=25V, ValueDisplayed=10uF
C2 C14: library part CMP-0002107-2, "Feedthru Capacitor, 0.47uF, 6.3V, SMD", Manufacturer=TDK, PartNumber=YFF18PW0J474M, Supplier Part Number 1=445-3028-1-ND
C3 C19: library part CMP-0009465-2, "CAP, CERM, 1 uF, 250 V, +/- 10%, X7R, 2220", Cap_Case=2220, Manufacturer=MuRata, PartNumber=GRM55DR72E105KW01L, Supplier Part Number 1=490-3550-1-ND, TempCo=X7R, Tolerance_%=10%, Value1="0.007086 ohm", Value2=250V, ValueDisplayed=1uF
C4 C5 C12: library part CMP-0008410-2, "CAP, CERM, 0.022 uF, 250 V, +/- 10%, X7R, 0805", Cap_Case=0805, Manufacturer="Taiyo Yuden", PartNumber=QMK212B7223KG-T, Supplier Part Number 1=587-1272-1-ND, TempCo=X7R, Tolerance_%=10%, Value1=Unknown, Value2=250V, ValueDisplayed=0.022uF
C6: library part CMP-0010616-1, "CAP, AL, 22 uF, 20 V, +/- 20%, 0.06 ohm, SMD", Cap_Case=F60, Manufacturer=Chemi-Con, PartNumber=APXH200ARA220MF60G, Supplier Part Number 1=565-3149-1-ND, Tolerance_%=20%, Value1="0.06 ohm", Value2=20V, ValueDisplayed=22uF
C7 C10 C18 C20 C21: library part CMP-0009193-2, "CAP, CERM, 0.22 uF, 250 V, +/- 10%, X7R, 1210", Cap_Case=1210, Manufacturer=MuRata, PartNumber=GRM32DR72E224KW01L, Supplier Part Number 1=490-3545-1-ND, TempCo=X7R, Tolerance_%=10%, Value1=Unknown, Value2=250V, ValueDisplayed=0.22uF
C13: library part CMP-0007404-4, "CAP, CERM, 0.1 uF, 25 V, +/- 10%, X7R, 0603", Cap_Case=0603, Manufacturer=MuRata, PartNumber=GRM188R71E104KA01D, Supplier Part Number 1=490-1524-1-ND, TempCo=X7R, Tolerance_%=10%, Value1=Unknown, Value2=25V, ValueDisplayed=0.1uF
C15 C16: library part CMP-0006207-2, "CAP, CERM, 10 pF, 50 V, +/- 5%, C0G/NP0, 0402", Cap_Case=0402, Manufacturer="Johanson Technology", PartNumber=500R07S100JV4T, TempCo=C0G/NP0, Tolerance_%=5%, Value1=Unknown, Value2=50V, ValueDisplayed=10pF
C17: library part CMP-0010617-1, "CAP, AL, 47 uF, 20 V, +/- 20%, 0.045 ohm, SMD", Cap_Case=H70, Manufacturer=Chemi-Con, PartNumber=APXH200ARA470MH70G, Supplier Part Number 1=565-3150-1-ND, Tolerance_%=20%, Value1="0.045 ohm", Value2=20V, ValueDisplayed=47uF
D1: library part CMP-0076946-1, "Diode, Schottky, 100 V, 0.25 A, SOD-323F", Manufacturer=Nexperia, Supplier Part Number 1=568-6017-1-ND, Value1=0.25A, Value2=0.85V
D2 D3: library part CMP-0002888-1, "LED, Green, SMD", Color=Green, Manufacturer=Lite-On, PartNumber=LTST-C170KGKT, Supplier Part Number 1=160-1414-1-ND, Value1=W, Value2=2V
FID1 FID2 FID3 FID4 FID5 FID6: library part CMP-0077181-1, "Fiducial mark.  There is nothing to buy or mount.", Manufacturer=N/A
H1 H2 H3 H4: library part CMP-0003617-1, "Machine Screw, Round, #4-40 x 1/4, Nylon, Philips panhead", Manufacturer="B&F Fastener Supply", Supplier Part Number 1=H542-ND
H5 H6 H7 H8: library part CMP-0003610-1, "Standoff, Hex, 0.5\"L #4-40 Nylon", Manufacturer=Keystone, PartNumber=1902C, Supplier Part Number 1=36-1902C-ND
J1: library part CMP-0075076-1, "Terminal Block, 2.54mm, 2x1, Brass, TH", Manufacturer="On-Shore Technology", PartNumber=OSTVN02A150, Supplier Part Number 1=ED10561-ND
J2 J5: library part CMP-0054973-1, "Terminal Block, 2x1, 5.08mm, TH", Manufacturer="TE Connectivity", PartNumber=282841-2, Supplier Part Number 1=A98342-ND
J3 J6 J7: library part CMP-0054576-1, "Header, 2.54 mm, 2x1, Gold, TH", Manufacturer="Sullins Connector Solutions", PartNumber=GBC02SAAN
J4: library part CMP-0054950-1, "Header, 100mil, 4x1, Tin, TH", Manufacturer="TE Connectivity", PartNumber=5-146278-4, Supplier Part Number 1=5-146278-4-ND
L2: library part CMP-0061062-1, "Inductor, Shielded, Composite, 4.7 uH, 10.5 A, 0.00889 ohm, SMD", Manufacturer=Coilcraft, PartNumber=XAL8080-472ME, Supplier Part Number 1=994-XAL8080-472MEB, Value1="0.00889 ohm", Value2=10.5A, ValueDisplayed=4.7uH
Logo1: library part CMP-0074847-1, "FCC_disclaimer"
Logo2: library part CMP-0074838-1, "Texas Instrument Corporate Signature"
Logo3: library part CMP-0074769-1
LOGO4 LOGO6 LOGO7 LOGO8: library part CMP-0074835-1, "IEC 61010-1 High Voltage Warning"
LOGO5 LOGO9: library part CMP-0074837-1, "IEC 61010-1 Hot Surface Warning"
LOGO10: library part CMP-0074844-1
NT1 NT2: library part CMP-0078142-1, "Single point connection between nets.", Manufacturer=N/A
Q1 Q2: library part CMP-0000972-2, "MOSFET, N-CH, 100 V, 36 A, 4.105x1.632mm", Alternate Manufacturer=None, Manufacturer=EPC, Supplier Part Number 1=917-1079-1-ND, Value2="7.5 nC"
R1 R2 R4 R8: library part CMP-0026992-3, "RES, 0, 5%, 0.1 W, AEC-Q200 Grade 0, 0402", Manufacturer=Panasonic, PartNumber=ERJ-2GE0R00X, Power_W=100mW, Supplier Part Number 1=P0.0JCT-ND, TempCo="600 ppm/C", Tolerance_%=5%, Value2=0.1W, Value_Code=0000, ValueDisplayed=0
R3 R10: library part CMP-0027011-4, "RES, 0, 5%, 0.05 W, AEC-Q200 Grade 1, 0201", Manufacturer=Panasonic, PartNumber=ERJ-1GE0R00C, Power_W=50mW, Supplier Part Number 1=P0.0AGCT-ND, TempCo="600 ppm/C", Tolerance_%=5%, Value2=0.05W, Value_Code=0000, ValueDisplayed=0
R6 R9: library part CMP-0026162-2, "RES, 20.0 k, 1%, 0.063 W, AEC-Q200 Grade 0, 0402", Manufacturer=Vishay-Dale, PartNumber=CRCW040220K0FKED, Power_W=63mW, Supplier Part Number 1=541-20.0KLCT-ND, TempCo="100 ppm/C", Tolerance_%=1%, Value2=0.063W, Value_Code=20k0, ValueDisplayed=20.0k
R7: library part CMP-0015203-2, "RES, 0.005, 1%, 1 W, 0612", Manufacturer="Susumu Co Ltd", Power_W=1W, Supplier Part Number 1=PRL1632.005FCT-ND, TempCo="350 ppm/C", Tolerance_%=1%, Value_Code=5L000, ValueDisplayed=0.005
R11 R12: library part CMP-0027269-3, "RES, 20.0 k, 1%, 0.05 W, 0201", Manufacturer=Vishay-Dale, PartNumber=CRCW020120K0FKED, Power_W=50mW, Supplier Part Number 1=541-20.0KAABCT-ND, TempCo="100 ppm/C", Tolerance_%=1%, Value2=0.05W, Value_Code=20k0, ValueDisplayed=20.0k
R13 R14: library part CMP-0002063-2, "TRIMMER 1M OHM 0.25W SMD", Manufacturer=Bourns, PartNumber=3224X-1-105E, Supplier Part Number 1=3224X-1-105ECT-ND
R15: library part CMP-0025729-4, "RES, 1.0 k, 5%, 0.1 W, AEC-Q200 Grade 0, 0603", Manufacturer=Vishay-Dale, PartNumber=CRCW06031K00JNEA, Power_W=100mW, Supplier Part Number 1=541-1.0KGCT-ND, TempCo="200 ppm/C", Tolerance_%=5%, Value2=0.1W, Value_Code=1k00, ValueDisplayed=1.0k
R16: library part CMP-0018574-3, "RES, 100 k, 5%, 0.25 W, AEC-Q200 Grade 0, 1206", Manufacturer=Vishay-Dale, PartNumber=CRCW1206100KJNEA, Power_W=250mW, Supplier Part Number 1=541-100KECT-ND, TempCo="200 ppm/C", Tolerance_%=5%, Value2=0.25W, Value_Code=100k
SH-J1: library part CMP-0003623-1, "Shunt, 100mil, Gold plated, Black", Alternate Manufacturer=3M, Alternate PartNumber=969102-0000-DA, Manufacturer=Samtec, Supplier Part Number 1=SNT-100-BK-G-ND
TP1: library part CMP-0055146-1, "Test Point, Compact, Yellow, TH", Color=Yellow, Manufacturer=Keystone, Supplier Part Number 1=36-5009-ND
TP2: library part CMP-0055142-1, "Test Point, Compact, Red, TH", Color=Red, Manufacturer=Keystone, Supplier Part Number 1=36-5005-ND
TP3 TP5 TP8 TP9 TP11 TP12: library part CMP-0003907-1, "PIGTAIL", Manufacturer="Texas Instruments", PartNumber=TESTPOINT_PIGTAIL
TP4 TP7 TP13: library part CMP-0055143-1, "Test Point, Compact, Black, TH", Color=Black, Manufacturer=Keystone, Supplier Part Number 1=36-5006-ND
TP6 TP10: library part CMP-0055137-1, "Test Point, Miniature, Red, TH", Color=Red, Manufacturer=Keystone, PartNumber=5000, Supplier Part Number 1=36-5000-ND
U1: library part CMP-0014092-2, "Advanced eGaN FET 300V Half-bridge Drive, RVR0019A (WQFN-19)", Alternate Manufacturer="Texas Instruments", PartNumber=LMG1210RVR
U2: library part CMP-0051898-1, "Dual Schmitt-Trigger Buffer, DBV0006A, LARGE T&R", F @ Nom Voltage(Max)(Mhz)=150, Generic Part Number=SN74LVC2G17, ICC @ Nom Voltage(Max)(mA)=0.01, Manufacturer="Texas Instruments", Operating Temperature Range(C)="-40 to 125,-40 to 85", Rating=Catalog, tpd @ Nom Voltage(Max)(ns)=9.3,5.7,5.4,4.3, Voltage(Nom)(V)=1.8,2.5,3.3,5
ZZ2: library part CMP-0077236-1
ZZ3: library part CMP-0077237-1
ZZ4: library part CMP-0077238-1

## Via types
v1: diameter 24, hole 12, Top Layer to Bottom Layer, tented both sides, 110 vias
v2: diameter 17, hole 7, Top Layer to Bottom Layer, tented both sides, 71 vias
v3: diameter 22, hole 12, Top Layer to Bottom Layer, tented both sides, 6 vias
v4: diameter 19.68, hole 7.87, Top Layer to Bottom Layer, 4 vias

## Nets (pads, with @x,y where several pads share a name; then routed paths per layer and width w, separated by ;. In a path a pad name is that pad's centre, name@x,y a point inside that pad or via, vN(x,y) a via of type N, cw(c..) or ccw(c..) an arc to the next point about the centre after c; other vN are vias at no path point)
5V_VCC: C1.1 C2.1 C2.2 C13.1 J3.2 J6.1 R15.1 TP1.1 U1.4 U2.5 | length 2341.2
  Top Layer w10: R15.1@101,1719 216,1604 J3.2@286,1604 ; J3.2@281,1609 326.51,1563.49 326.51,1469.35 310,1452.83 310,1026.5 316.5,1020 v2@350,1020 ; TP1.1@461,524 439.29,545.71 439.29,760.38 v2(501,822.09) ; C2.1@503.5,843 501,840.5 v2(501,822.09) ; U1.4@568.58,904.2 U1.4@568.58,904.62 ; 568.68,868.81 568.68,876.13 ; U1.4@568.68,904.2 568.68,876.13 ; v2(501,822.09) 502.4,822.09 515.11,809.38 554.89,809.38 566.5,820.98 C2.2@566.5,843 566.5,873.94 568.68,876.13
  Top Layer w12: C13.1@303,1020 303,940 314,929 U2.5@346.13,929
  Bottom Layer w10: v2@349,1021.74 v2(349,1021) 349,999 368,980 380.87,980 392,968.87 392,956 453.36,894.64 C1.1@453.36,824.06 ; TP1.1@461,524 476,539 853.29,539 918.29,474 J6.1@961,474 ; C1.1@475,821.09 500,821.09 v2(501,822.09)
11: U1.11
15: U1.15
EN: R1.2 R2.1 TP8.1 U2.6 | length 313.5
  Top Layer w12: U2.6@346.13,966.4 351.54,961 v2(373,961) R2.1@397.38,961
  Bottom Layer w12: TP8.1@244.21,816.64 273.62,846.06 273.62,879 288,879 ; R1.2@271,896 288,879 ; v2(373,961) 373,913 339,879 288,879
EN_IN: J3.1 J4.1 R1.1 R6.2 U2.1 | length 911
  Top Layer w10: J4.1@111,1404 211,1504 J3.1@286,1504 ; v2(200.19,964) 202.59,966.4 U2.1@237.87,966.4
  Bottom Layer w10: J4.1@101,1389.62 56.52,1345.14 56.52,1087.4 56,1086.88 56,1013.62 171.62,898 R1.1@206.38,898 ; R6.2@155,921 157.19,921 v2(200.19,964)
GND: C1.2 C2.3 C3.2 C4.2 C5.2 C6.2 C7.2 C10.2 C11.1 C12.2 C13.2 C15.1 C16.2 C17.2 C18.2 C19.2 C20.2 C21.2 D2.2 D3.2 J1.1 J2.2 J4.2 J4.3 J5.1 Q2.2 Q2.4 Q2.6 Q2.8 Q2.10 R6.1 R9.1 R13.3 R14.3 TP3.2 TP4.1 TP5.2 TP7.1 TP8.2 TP9.2 TP11.2 TP12.2 TP13.1 U1.3 U1.7 U1.20@549,949.47 U2.2 | length 849.5
  Top Layer w10: D2.2@335,1716 v3(367,1716) ; C2.3@548.89,858.71 U1.20@548.89,949.89 ; U1.20@572.52,949.89 U1.7@604.01,949.89 ; U1.7@604.12,949.47 623.07,949.47 627,945.54 v2(627,943) ; Q2.2@695,929 699.35,929 Q2.2@700.13,928.21
  Top Layer w12: v2(208,930) v2@213,930 ; U2.2@237.87,929 214,929 v2@213,930 ; C13.2@253.5,1020 v2(276,997.5) 286,987.5 286,945 v2(270,929) 269,930 v2@213,930 ; TP4.1@451,339 TP4.1@465,339 586.39,339 R13.3@610.61,314.79 ; v3(1081,404) 1090.21,413.21 R14.3@1201.39,413.21 ; v3(2109,1677) 2111.34,1674.66 D3.2@2111.34,1641
  Bottom Layer w10: R6.1@151,959 151,984
  Bottom Layer w12: J1.1@199,439 300.91,439 C11.1@305,434.91
  other v1: 2134,566 2184,566 2134,621 2184,621 2134,676 2184,676 376,698 2134,731 2189,731 376,734 1642.67,743 1708,743 1582,744 529,745 498,749 1375,754 1428.33,754 1481.67,754 1535,754 1372.67,788 1426,788 1479.33,788 1532.67,788 1586,803 1639.33,803 1704.67,803 1171,1389 1206,1389 952.1,1456.48 991.14,1456.48 1028.29,1459 1065.43,1459 954,1489 994,1489 1028.29,1489 1065.43,1489 1179,1525 1239,1525 1197,1603 1239,1605 1179,1695 1239,1695 1091,1775 1179,1775 1239,1775 1194.67,2080 1236.33,2080 1278,2080 1319.67,2080 1194.67,2120 1236.33,2120 1278,2120 1319.67,2120
  other v2: 526,844 544,844 746,887 714,888 777,889 808,890 701,906 731,906 763,906 794,908 825,909 647,1184 665,1184 683,1184 701,1184 731,1184 753,1184 776,1184 813,1186 831,1186 851,1186 955,1263 911,1264 1110,1270 1027,1274
  other v3: 151,997 384,1004
  other v4: 525.38,949.47 572.62,949.47
HB2: C14.1 C14.2 D1.1 TP3.1 U1.12 | length 457.1
  Top Layer w5: D1.1@410,1150.2 479.65,1150.2 ; TP3.1@452,1296 479.65,1268.35 479.65,1150.2 ; 501.71,1148.5 500.01,1150.2 479.65,1150.2
  Top Layer w10: 501.71,1148.5 C14.2@569,1148.5 ; U1.12@568.68,1053.8 C14.1@568.68,1085.19 ; C14.1@568.87,1085 590.51,1085 602.62,1097.11 602.62,1136.89 591.51,1148 578,1148 578,1147
HGATE: Q1.1 R3.2
HO: R3.1 TP5.1 U1.10 | length 211.8
  Top Layer w5: TP5.1@567,1196 TP5.1@567,1200 ; TP5.1@590,1189 606.5,1172.5 606.5,1163.3 615.12,1154.67 615.12,1039.22 U1.10@604.12,1028.21
  Top Layer w10: U1.10@604.12,1028.21 632.22,1028.21 R3.1@635.01,1031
